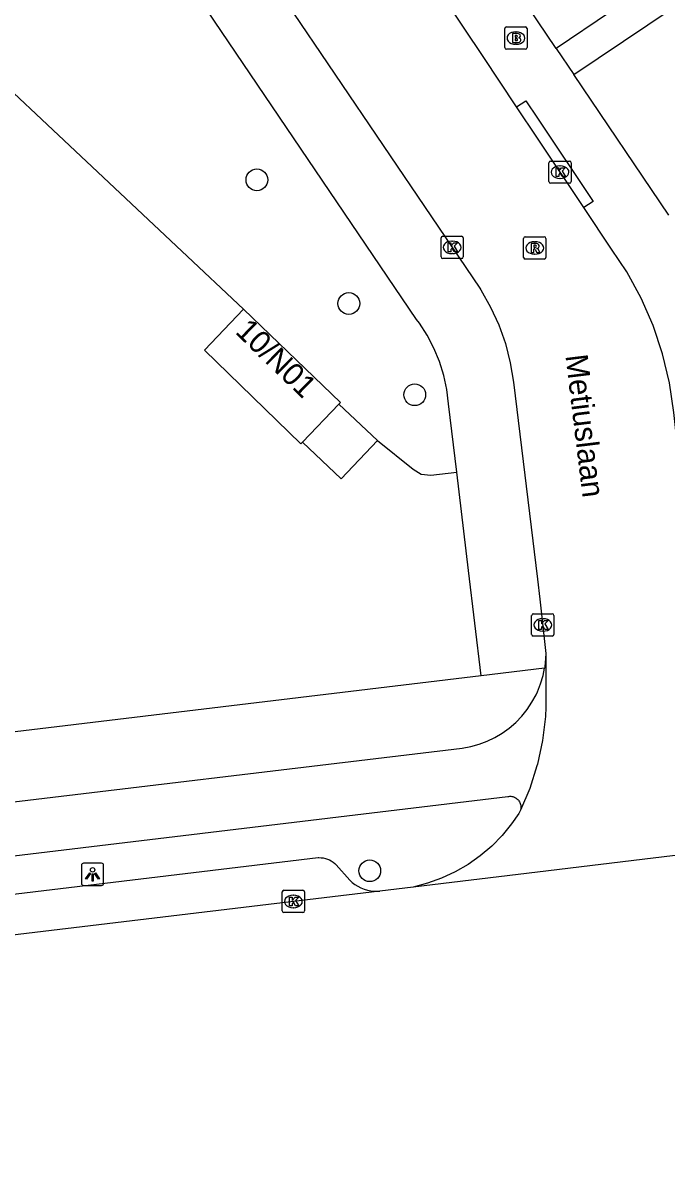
# Model space of a CAD drawing. Extents: x 159888 to 160757, y 384031 to 384746.
# Drawn here: x 160476.9 to 160505.8, y 384144.6 to 384196.5 of the extents above; entities that cross this region are included whole.
import ezdxf

# ---------------------------------------------------------------- set-up
doc = ezdxf.new("R2010")
doc.units = 0
for name, color, linetype in [('IMGEO_Boom', 7, 'Continuous'), ('IMGEO_Brandkraan', 7, 'Continuous'), ('IMGEO_Fietspad_open', 7, 'Continuous'), ('IMGEO_Groenvoorziening', 7, 'Continuous'), ('IMGEO_Kolk', 7, 'Continuous'), ('IMGEO_Lichtpunt', 7, 'Continuous'), ('IMGEO_Openbare_ruimte_label', 7, 'Continuous'), ('IMGEO_Pand', 7, 'Continuous'), ('IMGEO_Pand_nummerreeks', 7, 'Continuous'), ('IMGEO_Parkeervlak_open', 7, 'Continuous'), ('IMGEO_Rijbaan_lokaal_gesloten', 7, 'Continuous'), ('IMGEO_Rijbaan_lokaal_open', 7, 'Continuous'), ('IMGEO_Rioolput', 7, 'Continuous'), ('IMGEO_Voetpad_open', 7, 'Continuous')]:
    doc.layers.add(name, color=color, linetype=linetype)

msp = doc.modelspace()

# ---------------------------------------------------------------- linework, layer by layer
at = {"layer": 'IMGEO_Boom'}
for centre in [(160487.383, 384189.429), (160491.518, 384183.871), (160494.482, 384179.773), (160492.459, 384158.379)]:
    msp.add_circle(centre, 0.489, dxfattribs=at)
at = {"layer": 'IMGEO_Brandkraan'}
for p, q in [((160498.532, 384195.374), (160498.532, 384196.226)), ((160498.607, 384196.3), (160499.459, 384196.3)), ((160499.02, 384196.08), (160499.045, 384196.08)), ((160499.533, 384196.226), (160499.533, 384195.374)), ((160499.459, 384195.3), (160498.607, 384195.3)), ((160499.043, 384195.52), (160499.018, 384195.52))]:
    msp.add_line(p, q, dxfattribs=at)
for points in [[(160498.532, 384195.374), (160498.532, 384196.226)], [(160498.607, 384196.3), (160499.459, 384196.3)], [(160499.533, 384196.226), (160499.533, 384195.374)], [(160498.88, 384196), (160498.88, 384195.6), (160499.093, 384195.6)], [(160499.111, 384196), (160498.88, 384196)], [(160499.059, 384195.919), (160499.005, 384195.919), (160499.005, 384195.843)], [(160499.005, 384195.843), (160499.058, 384195.843)], [(160499.067, 384195.767), (160499.005, 384195.767), (160499.005, 384195.686)], [(160499.005, 384195.686), (160499.067, 384195.686)], [(160499.459, 384195.3), (160498.607, 384195.3)]]:
    msp.add_lwpolyline(points, dxfattribs=at)
for centre, radius, start, end in [((160498.609, 384196.224), 0.0765, 91.552, 178.448), ((160498.609, 384196.224), 0.0765, 91.552, 178.448), ((160499.457, 384196.224), 0.0765, 1.552, 88.448), ((160499.457, 384196.224), 0.0765, 1.552, 88.448), ((160499.06, 384195.881), 0.0379, 267.8285, 90.9355), ((160499.068, 384195.726), 0.0404, 269.8759, 90.5077), ((160499.099, 384195.851), 0.251, 268.6676, 293.5347), ((160499.115, 384195.855), 0.145, 59.4692, 91.5367), ((160499.14, 384195.902), 0.0922, 285.5137, 58.1501), ((160499.145, 384195.71), 0.105, 301.3115, 78.989), ((160498.609, 384195.376), 0.0765, 181.552, 268.448), ((160498.609, 384195.376), 0.0765, 181.552, 268.448), ((160499.457, 384195.376), 0.0765, 271.552, 358.448), ((160499.457, 384195.376), 0.0765, 271.552, 358.448)]:
    msp.add_arc(centre, radius, start, end, dxfattribs=at)
for centre, major_axis, ratio, start_param, end_param in [((160499.019, 384195.8), (-0.387, 0.002), 0.722429, 4.712389, 7.853982), ((160499.044, 384195.8), (-0.39, 0.002), 0.717154, 1.570796, 4.712389)]:
    msp.add_ellipse(centre, major_axis=major_axis, ratio=ratio, start_param=start_param, end_param=end_param, dxfattribs=at)
at = {"layer": 'IMGEO_Fietspad_open'}
for points in [[(160500.377, 384168.143), (160500.369, 384167.924), (160500.327, 384167.538), (160500.317, 384167.486)], [(160397.757, 384144.577), (160402.131, 384147.008), (160404.263, 384148.273), (160408.933, 384150.481), (160414.196, 384152.415), (160420.542, 384154.247), (160427.484, 384155.614), (160496.618, 384163.892), (160497, 384163.961), (160497.373, 384164.063), (160497.737, 384164.199), (160498.086, 384164.366), (160498.419, 384164.565), (160498.734, 384164.792), (160499.026, 384165.046), (160499.295, 384165.325), (160499.538, 384165.627), (160499.753, 384165.95), (160499.938, 384166.291), (160500, 384166.424), (160500.142, 384166.785), (160500.252, 384167.157), (160500.317, 384167.486)], [(160427.759, 384153.215), (160498.671, 384161.716), (160498.713, 384161.723), (160498.757, 384161.726), (160498.8, 384161.725), (160498.844, 384161.721), (160498.886, 384161.712), (160498.928, 384161.7), (160498.969, 384161.684), (160499.008, 384161.664), (160499.045, 384161.642), (160499.08, 384161.615), (160499.112, 384161.586), (160499.142, 384161.554), (160499.169, 384161.52), (160499.192, 384161.483), (160499.212, 384161.445), (160499.229, 384161.404), (160499.242, 384161.363), (160499.251, 384161.32), (160499.256, 384161.277), (160499.258, 384161.233), (160499.255, 384161.19), (160499.249, 384161.146), (160499.239, 384161.104)]]:
    msp.add_lwpolyline(points, dxfattribs=at)
at = {"layer": 'IMGEO_Groenvoorziening'}
for points in [[(160472.691, 384191.58), (160475.677, 384194.048), (160486.78, 384183.613)], [(160492.813, 384177.71), (160494.41, 384176.424), (160494.765, 384176.208), (160495.213, 384176.159), (160496.371, 384176.297)]]:
    msp.add_lwpolyline(points, dxfattribs=at)
at = {"layer": 'IMGEO_Kolk'}
for p, q in [((160500.515, 384189.347), (160500.515, 384190.199)), ((160500.59, 384190.273), (160501.442, 384190.273)), ((160501.003, 384190.053), (160501.028, 384190.053)), ((160501.516, 384190.199), (160501.516, 384189.347)), ((160501.026, 384189.493), (160501.001, 384189.493)), ((160501.442, 384189.273), (160500.59, 384189.273)), ((160495.664, 384185.968), (160495.664, 384186.82)), ((160495.739, 384186.894), (160496.591, 384186.894)), ((160496.665, 384186.82), (160496.665, 384185.968)), ((160496.152, 384186.674), (160496.177, 384186.674)), ((160496.591, 384185.894), (160495.739, 384185.894)), ((160496.175, 384186.114), (160496.15, 384186.114)), ((160499.74, 384169), (160499.74, 384169.852)), ((160499.815, 384169.926), (160500.667, 384169.926)), ((160500.228, 384169.706), (160500.253, 384169.706)), ((160500.741, 384169.852), (160500.741, 384169)), ((160500.251, 384169.146), (160500.226, 384169.146)), ((160500.667, 384168.926), (160499.815, 384168.926)), ((160488.524, 384156.574), (160488.524, 384157.426)), ((160488.599, 384157.5), (160489.451, 384157.5)), ((160489.012, 384157.28), (160489.037, 384157.28)), ((160489.525, 384157.426), (160489.525, 384156.574)), ((160489.035, 384156.72), (160489.01, 384156.72)), ((160489.451, 384156.5), (160488.599, 384156.5))]:
    msp.add_line(p, q, dxfattribs=at)
for points in [[(160500.515, 384189.347), (160500.515, 384190.199)], [(160500.59, 384190.273), (160501.442, 384190.273)], [(160500.836, 384189.973), (160500.959, 384189.973), (160500.959, 384189.822), (160501.089, 384189.973), (160501.253, 384189.973), (160501.107, 384189.822), (160501.26, 384189.573), (160501.108, 384189.573), (160501.023, 384189.737), (160500.959, 384189.67), (160500.959, 384189.573), (160500.836, 384189.573), (160500.836, 384189.973)], [(160501.516, 384190.199), (160501.516, 384189.347)], [(160501.442, 384189.273), (160500.59, 384189.273)], [(160495.664, 384185.968), (160495.664, 384186.82)], [(160495.739, 384186.894), (160496.591, 384186.894)], [(160496.665, 384186.82), (160496.665, 384185.968)], [(160495.985, 384186.594), (160496.108, 384186.594), (160496.108, 384186.443), (160496.238, 384186.594), (160496.402, 384186.594), (160496.256, 384186.443), (160496.409, 384186.194), (160496.257, 384186.194), (160496.172, 384186.358), (160496.108, 384186.291), (160496.108, 384186.194), (160495.985, 384186.194), (160495.985, 384186.594)], [(160496.591, 384185.894), (160495.739, 384185.894)], [(160499.74, 384169), (160499.74, 384169.852)], [(160499.815, 384169.926), (160500.667, 384169.926)], [(160500.061, 384169.626), (160500.184, 384169.626), (160500.184, 384169.475), (160500.314, 384169.626), (160500.478, 384169.626), (160500.332, 384169.475), (160500.485, 384169.226), (160500.333, 384169.226), (160500.248, 384169.39), (160500.184, 384169.323), (160500.184, 384169.226), (160500.061, 384169.226), (160500.061, 384169.626)], [(160500.741, 384169.852), (160500.741, 384169)], [(160500.667, 384168.926), (160499.815, 384168.926)], [(160488.524, 384156.574), (160488.524, 384157.426)], [(160488.599, 384157.5), (160489.451, 384157.5)], [(160488.845, 384157.2), (160488.968, 384157.2), (160488.968, 384157.049), (160489.098, 384157.2), (160489.262, 384157.2), (160489.116, 384157.049), (160489.269, 384156.8), (160489.117, 384156.8), (160489.032, 384156.964), (160488.968, 384156.897), (160488.968, 384156.8), (160488.845, 384156.8), (160488.845, 384157.2)], [(160489.525, 384157.426), (160489.525, 384156.574)], [(160489.451, 384156.5), (160488.599, 384156.5)]]:
    msp.add_lwpolyline(points, dxfattribs=at)
for centre, start, end in [((160500.592, 384190.197), 91.552, 178.448), ((160500.592, 384190.197), 91.552, 178.448), ((160501.44, 384190.197), 1.552, 88.448), ((160501.44, 384190.197), 1.552, 88.448), ((160500.592, 384189.349), 181.552, 268.448), ((160500.592, 384189.349), 181.552, 268.448), ((160501.44, 384189.349), 271.552, 358.448), ((160501.44, 384189.349), 271.552, 358.448), ((160495.741, 384186.818), 91.552, 178.448), ((160495.741, 384186.818), 91.552, 178.448), ((160496.589, 384186.818), 1.552, 88.448), ((160496.589, 384186.818), 1.552, 88.448), ((160495.741, 384185.97), 181.552, 268.448), ((160495.741, 384185.97), 181.552, 268.448), ((160496.589, 384185.97), 271.552, 358.448), ((160496.589, 384185.97), 271.552, 358.448), ((160499.817, 384169.85), 91.552, 178.448), ((160499.817, 384169.85), 91.552, 178.448), ((160500.665, 384169.85), 1.552, 88.448), ((160500.665, 384169.85), 1.552, 88.448), ((160499.817, 384169.002), 181.552, 268.448), ((160499.817, 384169.002), 181.552, 268.448), ((160500.665, 384169.002), 271.552, 358.448), ((160500.665, 384169.002), 271.552, 358.448), ((160488.601, 384157.424), 91.552, 178.448), ((160488.601, 384157.424), 91.552, 178.448), ((160489.449, 384157.424), 1.552, 88.448), ((160489.449, 384157.424), 1.552, 88.448), ((160488.601, 384156.576), 181.552, 268.448), ((160488.601, 384156.576), 181.552, 268.448), ((160489.449, 384156.576), 271.552, 358.448), ((160489.449, 384156.576), 271.552, 358.448)]:
    msp.add_arc(centre, 0.0765, start, end, dxfattribs=at)
for centre, major_axis, ratio, start_param, end_param in [((160501.002, 384189.773), (-0.387, 0.002), 0.722429, 4.712389, 7.853982), ((160501.027, 384189.773), (-0.39, 0.002), 0.717154, 1.570796, 4.712389), ((160496.151, 384186.394), (-0.387, 0.002), 0.722429, 4.712389, 7.853982), ((160496.176, 384186.394), (-0.39, 0.002), 0.717154, 1.570796, 4.712389), ((160500.227, 384169.426), (-0.387, 0.002), 0.722429, 4.712389, 7.853982), ((160500.252, 384169.426), (-0.39, 0.002), 0.717154, 1.570796, 4.712389), ((160489.011, 384157), (-0.387, 0.002), 0.722429, 4.712389, 7.853982), ((160489.036, 384157), (-0.39, 0.002), 0.717154, 1.570796, 4.712389)]:
    msp.add_ellipse(centre, major_axis=major_axis, ratio=ratio, start_param=start_param, end_param=end_param, dxfattribs=at)
at = {"layer": 'IMGEO_Lichtpunt'}
for p, q in [((160480.397, 384158.718), (160479.589, 384158.718)), ((160480.397, 384158.718), (160479.589, 384158.718)), ((160479.495, 384158.623), (160479.495, 384157.816)), ((160479.495, 384158.623), (160479.495, 384157.816)), ((160480.491, 384157.816), (160480.491, 384158.623)), ((160480.491, 384157.816), (160480.491, 384158.623)), ((160479.589, 384157.722), (160480.397, 384157.722)), ((160479.589, 384157.722), (160480.397, 384157.722))]:
    msp.add_line(p, q, dxfattribs=at)
for points in [[(160479.869, 384158.287), (160479.908, 384158.259), (160479.72, 384157.997), (160479.682, 384158.024), (160479.869, 384158.287)], [(160479.971, 384158.239), (160480.018, 384158.239), (160480.018, 384157.917), (160479.971, 384157.917), (160479.971, 384158.239)], [(160480.081, 384158.259), (160480.119, 384158.286), (160480.306, 384158.024), (160480.267, 384157.996), (160480.081, 384158.259)]]:
    msp.add_lwpolyline(points, dxfattribs=at)
msp.add_circle((160479.994, 384158.421), 0.0994, dxfattribs=at)
for centre, start, end in [((160479.589, 384158.623), 90, 180), ((160479.589, 384158.623), 90, 180), ((160480.397, 384158.623), 0, 90), ((160480.397, 384158.623), 0, 90), ((160479.589, 384157.816), 180, 270), ((160479.589, 384157.816), 180, 270), ((160480.397, 384157.816), 270, 0), ((160480.397, 384157.816), 270, 360)]:
    msp.add_arc(centre, 0.0946, start, end, dxfattribs=at)
at = {"layer": 'IMGEO_Pand'}
for points in [[(160489.431, 384177.643), (160489.36, 384177.569), (160485.029, 384181.774), (160486.78, 384183.613)], [(160486.78, 384183.613), (160491.144, 384179.427), (160491.067, 384179.347)], [(160489.431, 384177.643), (160491.067, 384179.347)]]:
    msp.add_lwpolyline(points, dxfattribs=at)
at = {"layer": 'IMGEO_Parkeervlak_open'}
msp.add_lwpolyline([(160427.443, 384151.436), (160490.133, 384158.969), (160490.176, 384158.97), (160490.273, 384158.967), (160490.368, 384158.955), (160490.462, 384158.934), (160490.554, 384158.906), (160490.643, 384158.869), (160490.728, 384158.824), (160490.809, 384158.772), (160490.885, 384158.713), (160490.955, 384158.647), (160491.556, 384157.963), (160491.67, 384157.859), (160491.793, 384157.765), (160491.924, 384157.683), (160492.061, 384157.613), (160492.205, 384157.556), (160492.352, 384157.511), (160492.504, 384157.48), (160492.657, 384157.463), (160492.811, 384157.459), (160492.911, 384157.464)], dxfattribs=at)
at = {"layer": 'IMGEO_Rijbaan_lokaal_gesloten'}
for points in [[(160516.108, 384160.265), (160500, 384158.317), (160494.41, 384157.644)], [(160492.911, 384157.464), (160427.962, 384149.681), (160425.051, 384149.307)], [(160494.41, 384157.644), (160492.911, 384157.464)]]:
    msp.add_lwpolyline(points, dxfattribs=at)
at = {"layer": 'IMGEO_Rijbaan_lokaal_open'}
for points in [[(160501.631, 384194.166), (160526.072, 384210.572)], [(160499.06, 384192.709), (160497.556, 384194.968), (160493.2, 384201.491), (160489.717, 384206.618), (160488.881, 384207.593)], [(160483.05, 384204.786), (160483.161, 384204.745), (160483.396, 384204.636), (160483.62, 384204.507), (160483.831, 384204.358), (160484.029, 384204.191), (160484.21, 384204.007), (160484.375, 384203.808), (160497.404, 384184.565), (160497.456, 384184.484), (160497.894, 384183.713), (160498.263, 384182.907), (160498.557, 384182.071), (160498.776, 384181.212), (160498.917, 384180.337), (160500, 384171.476), (160500.107, 384170.589), (160500.377, 384168.143)], [(160505.914, 384187.834), (160501.631, 384194.166)], [(160502.084, 384188.18), (160500, 384191.296), (160499.06, 384192.709)], [(160507.227, 384169.019), (160507.226, 384169.022), (160506.134, 384178.968), (160505.94, 384180.299), (160505.629, 384181.607), (160505.201, 384182.882), (160504.662, 384184.113), (160504.014, 384185.292), (160503.336, 384186.31), (160502.084, 384188.18)], [(160500.377, 384168.143), (160500.379, 384165.727), (160500.355, 384165.318), (160500.226, 384164.24), (160500, 384163.177), (160499.976, 384163.088), (160499.652, 384162.08), (160499.239, 384161.104)], [(160499.239, 384161.104), (160499.162, 384160.948), (160498.84, 384160.483), (160498.414, 384159.964), (160497.943, 384159.485), (160497.431, 384159.05), (160496.882, 384158.663), (160496.301, 384158.326), (160495.692, 384158.043), (160495.06, 384157.815), (160494.41, 384157.644)]]:
    msp.add_lwpolyline(points, dxfattribs=at)
at = {"layer": 'IMGEO_Rioolput'}
for p, q in [((160499.378, 384185.941), (160499.378, 384186.793)), ((160499.453, 384186.867), (160500.305, 384186.867)), ((160500.379, 384186.793), (160500.379, 384185.941)), ((160499.866, 384186.647), (160499.891, 384186.647)), ((160500.305, 384185.867), (160499.453, 384185.867)), ((160499.889, 384186.087), (160499.864, 384186.087))]:
    msp.add_line(p, q, dxfattribs=at)
for points in [[(160499.378, 384185.941), (160499.378, 384186.793)], [(160499.453, 384186.867), (160500.305, 384186.867)], [(160500.379, 384186.793), (160500.379, 384185.941)], [(160499.967, 384186.565), (160499.715, 384186.567), (160499.715, 384186.167)], [(160499.715, 384186.167), (160499.839, 384186.167), (160499.839, 384186.329), (160499.85, 384186.329)], [(160499.893, 384186.486), (160499.839, 384186.486), (160499.839, 384186.405)], [(160499.839, 384186.405), (160499.891, 384186.405)], [(160499.897, 384186.3), (160499.968, 384186.167), (160500.108, 384186.167), (160500.043, 384186.293)], [(160500.305, 384185.867), (160499.453, 384185.867)]]:
    msp.add_lwpolyline(points, dxfattribs=at)
for centre, radius, start, end in [((160499.455, 384186.791), 0.0765, 91.552, 178.448), ((160499.455, 384186.791), 0.0765, 91.552, 178.448), ((160500.303, 384186.791), 0.0765, 1.552, 88.448), ((160500.303, 384186.791), 0.0765, 1.552, 88.448), ((160499.849, 384186.276), 0.0533, 26.0293, 88.6989), ((160499.875, 384186.594), 0.19, 274.7715, 282.9687), ((160499.899, 384186.39), 0.0964, 77.0061, 93.1865), ((160499.913, 384186.447), 0.0378, 276.6634, 79.6772), ((160499.966, 384186.455), 0.109, 350.3612, 89.416), ((160499.964, 384186.455), 0.112, 277.5842, 350.9817), ((160499.948, 384186.24), 0.108, 29.5134, 73.7905), ((160499.455, 384185.943), 0.0765, 181.552, 268.448), ((160499.455, 384185.943), 0.0765, 181.552, 268.448), ((160500.303, 384185.943), 0.0765, 271.552, 358.448), ((160500.303, 384185.943), 0.0765, 271.552, 358.448)]:
    msp.add_arc(centre, radius, start, end, dxfattribs=at)
for centre, major_axis, ratio, start_param, end_param in [((160499.865, 384186.367), (-0.387, 0.002), 0.722429, 4.712389, 7.853982), ((160499.89, 384186.367), (-0.39, 0.002), 0.717154, 1.570796, 4.712389)]:
    msp.add_ellipse(centre, major_axis=major_axis, ratio=ratio, start_param=start_param, end_param=end_param, dxfattribs=at)
at = {"layer": 'IMGEO_Voetpad_open'}
for points in [[(160500.839, 384195.337), (160500, 384196.578), (160463.867, 384250), (160432.977, 384295.669)], [(160496.371, 384176.297), (160496.006, 384179.357), (160495.925, 384180.003), (160495.787, 384180.64), (160495.592, 384181.262), (160495.343, 384181.864), (160495.041, 384182.441), (160494.689, 384182.989), (160494.565, 384183.158), (160480.257, 384204.274)], [(160505.731, 384198.646), (160500.839, 384195.337)], [(160500.839, 384195.337), (160501.631, 384194.166)], [(160499.06, 384192.709), (160499.476, 384192.985), (160500, 384192.201), (160502.5, 384188.456), (160502.084, 384188.18)], [(160491.067, 384179.347), (160492.813, 384177.71)], [(160492.813, 384177.71), (160491.169, 384175.986), (160489.431, 384177.643)], [(160497.469, 384167.144), (160496.899, 384171.869), (160496.371, 384176.297)], [(160497.469, 384167.144), (160440.695, 384160.33)], [(160500.317, 384167.486), (160497.469, 384167.144)]]:
    msp.add_lwpolyline(points, dxfattribs=at)

# ---------------------------------------------------------------- texts
at = {"layer": 'IMGEO_Openbare_ruimte_label'}
msp.add_text('Metiuslaan', height=1, rotation=276.9474, dxfattribs=at).set_placement((160501.256, 384181.532))
at = {"layer": 'IMGEO_Pand_nummerreeks'}
msp.add_text('10/N01', height=1, rotation=315.8479, dxfattribs=at).set_placement((160486.368, 384182.564))

doc.saveas('drawing.dxf')
